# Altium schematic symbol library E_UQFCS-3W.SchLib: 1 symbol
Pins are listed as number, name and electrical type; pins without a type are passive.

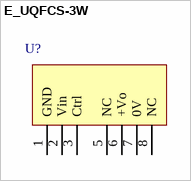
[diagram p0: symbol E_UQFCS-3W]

## E_UQFCS-3W
designator U?
footprint E_UQFCS-3W
pins: 1 GND, 2 Vin, 3 Ctrl, 5 NC, 6 +Vo, 7 0V, 8 NC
